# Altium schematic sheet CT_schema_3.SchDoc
size 608 x 329 mm
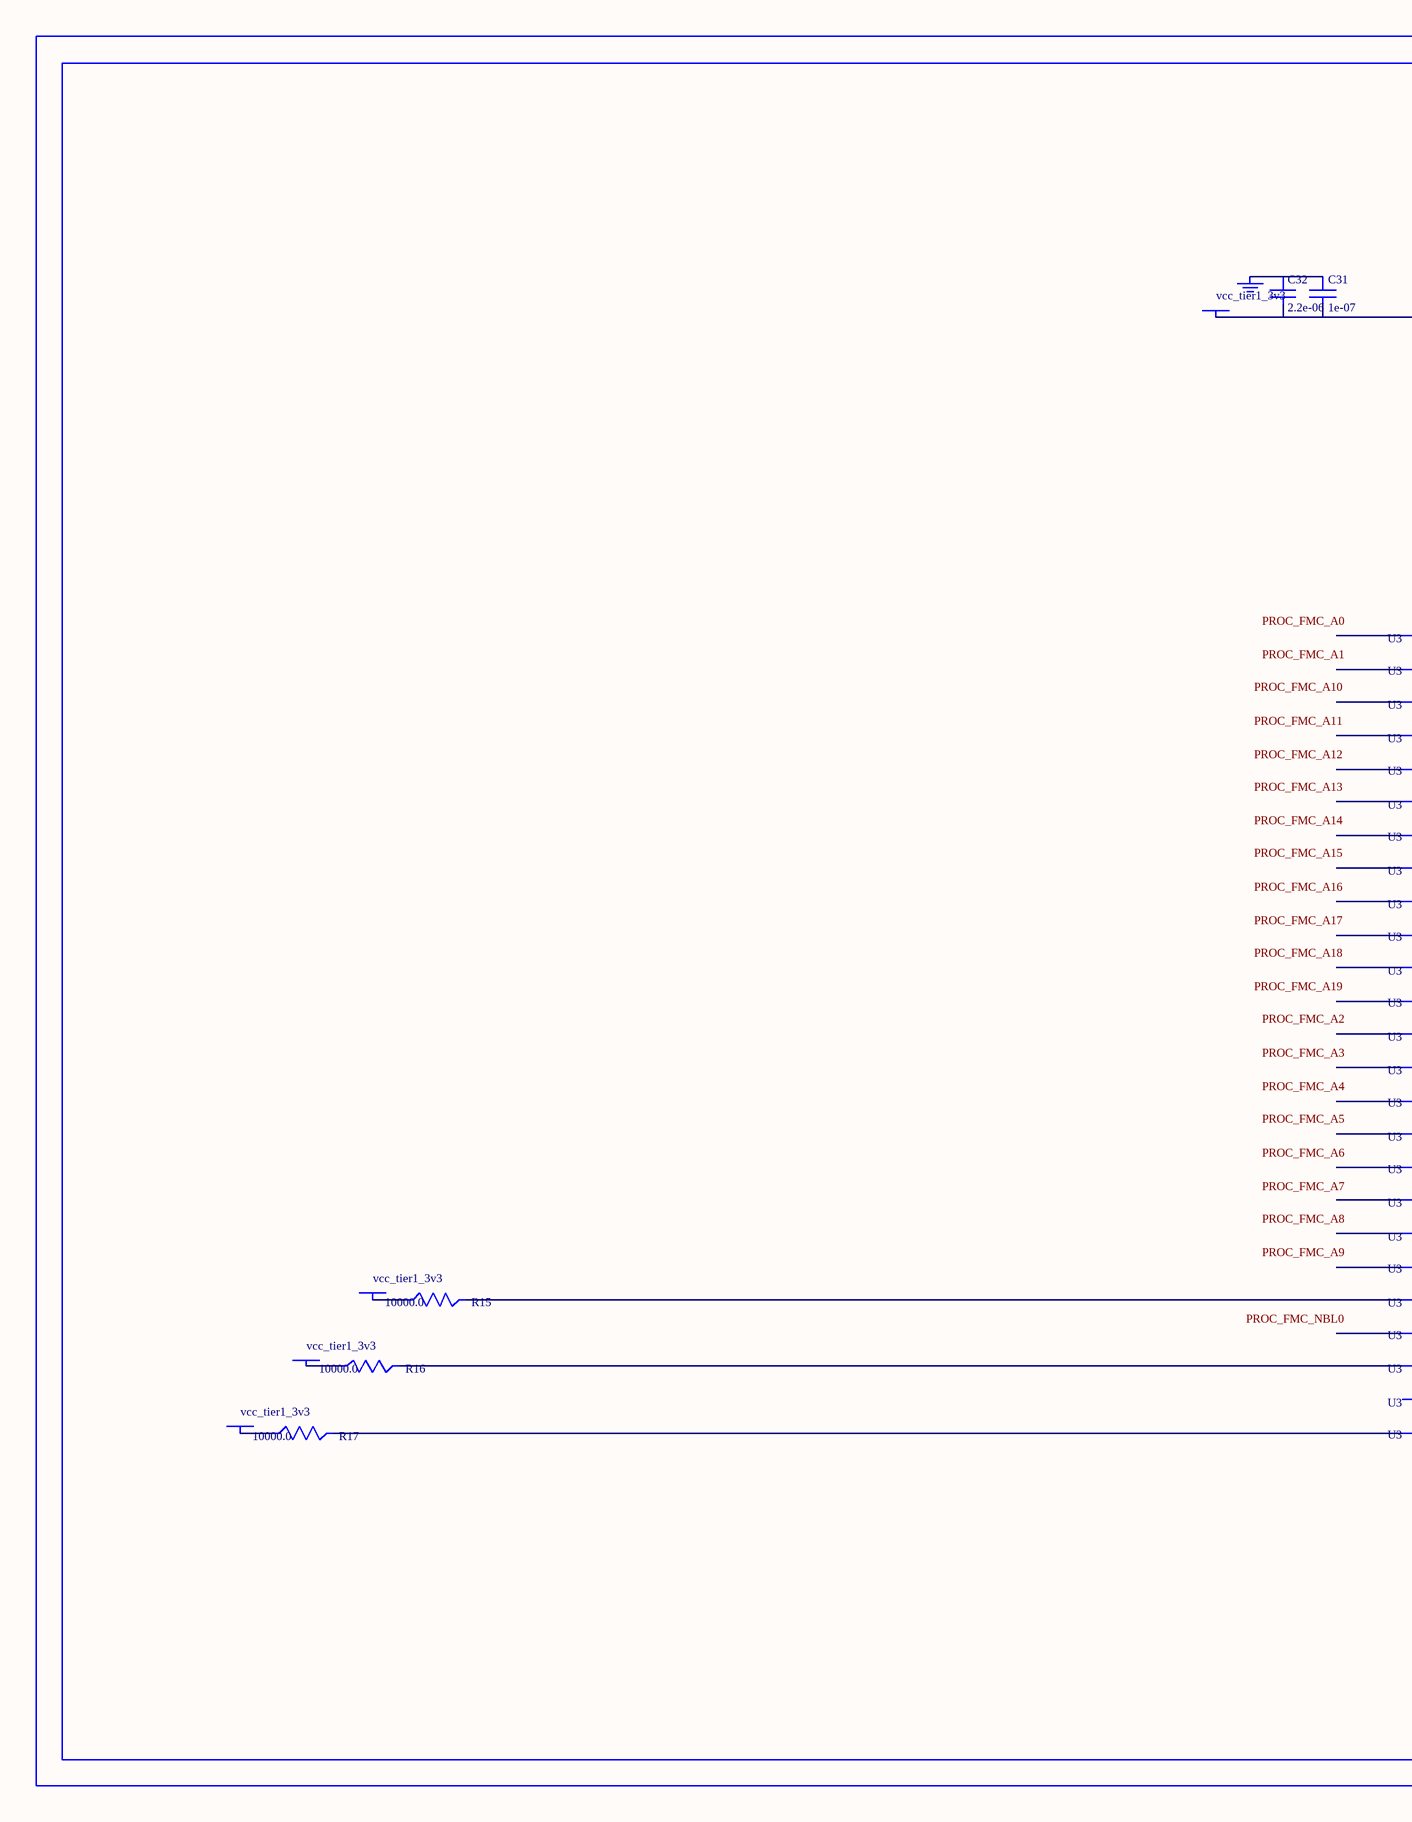
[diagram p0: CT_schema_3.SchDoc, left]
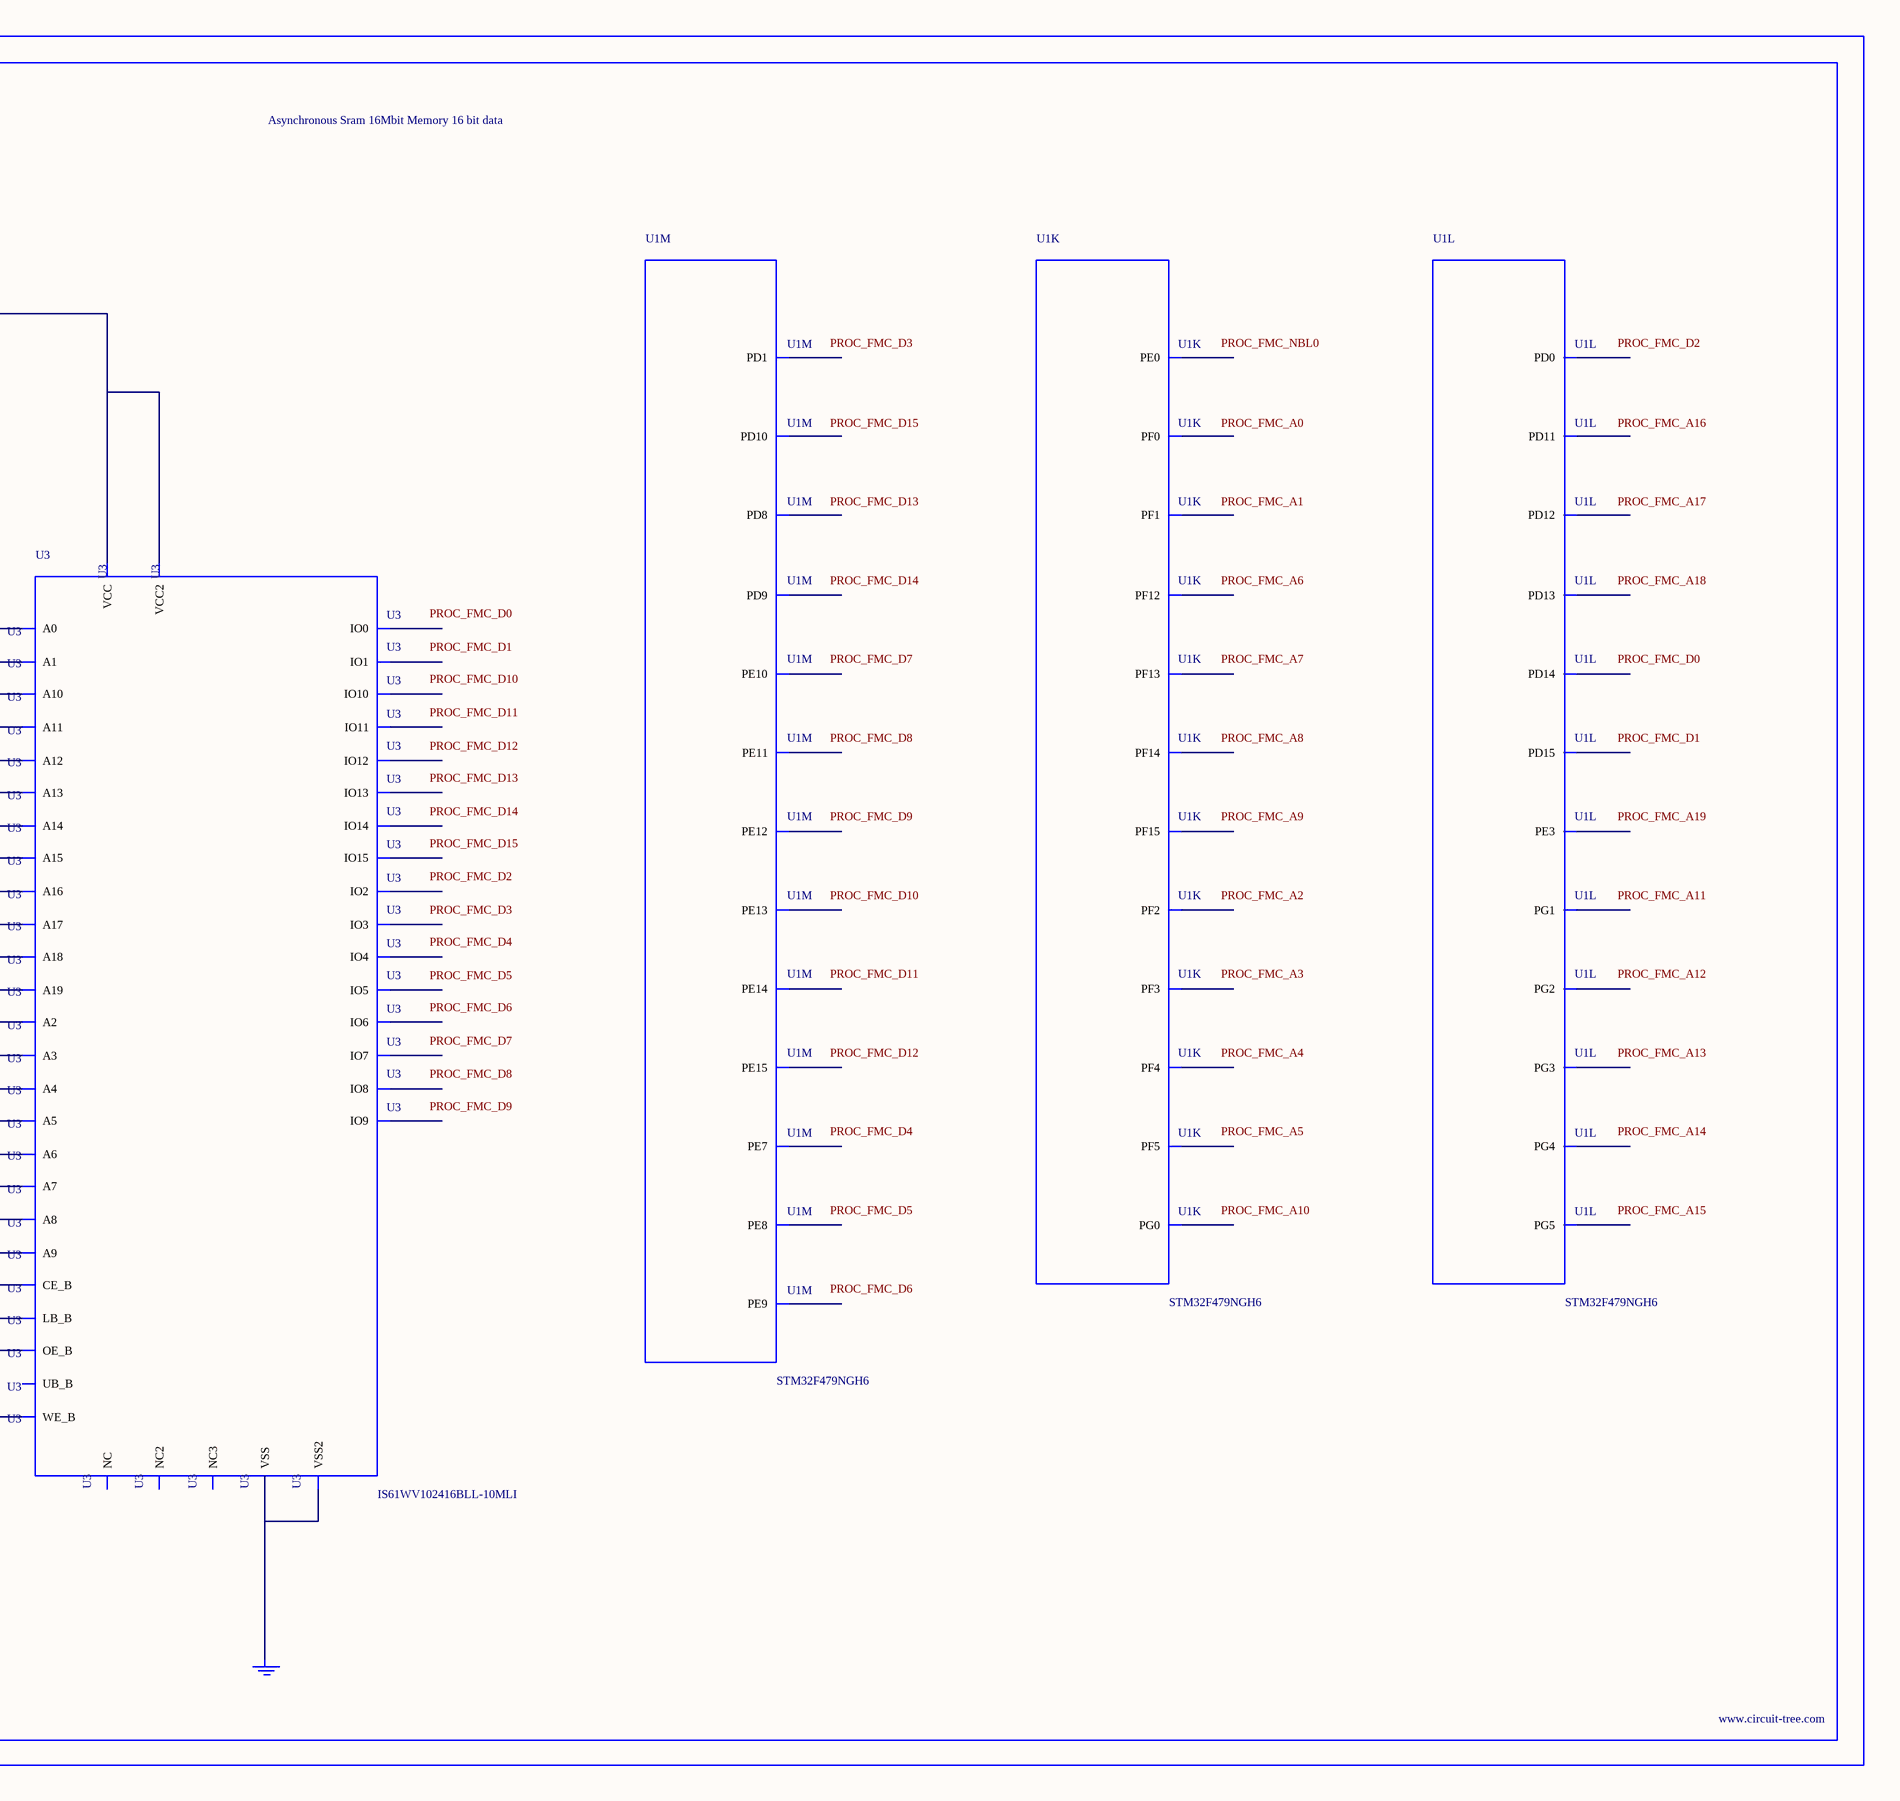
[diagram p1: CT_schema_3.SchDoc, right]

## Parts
BORDER2  (no value)
C31  1e-07  [C0402]
C32  2.2e-06  [C0603]
GND_INSTANCE_2_0  (no value)
GND_INSTANCE_2_1  (no value)
POWER_INSTANCE_2_0  vcc_tier1_3v3
POWER_INSTANCE_2_1  vcc_tier1_3v3
POWER_INSTANCE_2_2  vcc_tier1_3v3
POWER_INSTANCE_2_3  vcc_tier1_3v3
R15  10000.0  [R0603]
R16  10000.0  [R0603]
R17  10000.0  [R0603]
U1  STM32F479NGH6  [TFBGA216]  (parts K,L,M of 15)
U3  IS61WV102416BLL-10MLI  [IS61WV102416BLL-10MLI]

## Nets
NetC31_1: C31.1 C32.1 GND_INSTANCE_2_0.0(GND)
NetC31_2: C31.2 C32.2 POWER_INSTANCE_2_0.0(PWR) U3.D6(VCC) U3.E1(VCC2)
NetGND_INSTANCE_2_1_0: GND_INSTANCE_2_1.0(GND) U3.D1(VSS) U3.E6(VSS2)
NetPOWER_INSTANCE_2_1_0: POWER_INSTANCE_2_1.0(PWR) R15.1
NetPOWER_INSTANCE_2_2_0: POWER_INSTANCE_2_2.0(PWR) R16.1
NetPOWER_INSTANCE_2_3_0: POWER_INSTANCE_2_3.0(PWR) R17.1
NetR15_2: R15.2 U3.B5(CE_B)
NetR16_2: R16.2 U3.A2(OE_B)
NetR17_2: R17.2 U3.G5(WE_B)

Not connected (* = marked no-connect by the designer): U1 A2(PE3) A6(PE0) B12(PD0) C12(PD1) D2(PF0) E2(PF1) G2(PF2) H2(PF3) J2(PF4) K3(PF5) K13(PD15) K15(PD10) L12(PD14) L14(PD9) L15(PD8) M6(PF12) M7(PG1) M8(PF15) M10(PD12) M11(PD13) M12(PG3) M13(PG2) N6(PF13) N7(PG0) N9(PE8) N10(PD11) N11(PG5) N12(PG4) P6(PF14) P9(PE9) P10(PE11) P11(PE14) R8(PE7) R9(PE10) R10(PE12) R11(PE15) R12(PE13); U3 A1(LB_B) A3(A0) A4(A1) A5(A2) A6(NC) B1(IO8) B2(UB_B) B3(A3) B4(A4) B6(IO0) C1(IO9) C2(IO10) C3(A5) C4(A6) C5(IO1) C6(IO2) D2(IO11) D3(A17) D4(A7) D5(IO3) E2(IO12) E3(NC2) E4(A16) E5(IO4) F1(IO14) F2(IO13) F3(A14) F4(A15) F5(IO5) F6(IO6) G1(IO15) G2(A19) G3(A12) G4(A13) G6(IO7) H1(A18) H2(A8) H3(A9) H4(A10) H5(A11) H6(NC3)

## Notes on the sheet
- Labels drawn without touching a wire or pin: PROC_FMC_A0, PROC_FMC_A1, PROC_FMC_A2, PROC_FMC_A3, PROC_FMC_A4, PROC_FMC_A5, PROC_FMC_A6, PROC_FMC_A7, PROC_FMC_A8, PROC_FMC_A9, PROC_FMC_A10, PROC_FMC_A11, PROC_FMC_A12, PROC_FMC_A13, PROC_FMC_A14, PROC_FMC_A15, PROC_FMC_A16, PROC_FMC_A17, PROC_FMC_A18, PROC_FMC_A19, PROC_FMC_D0, PROC_FMC_D1, PROC_FMC_D2, PROC_FMC_D3, PROC_FMC_D4, PROC_FMC_D5, PROC_FMC_D6, PROC_FMC_D7, PROC_FMC_D8, PROC_FMC_D9, PROC_FMC_D10, PROC_FMC_D11, PROC_FMC_D12, PROC_FMC_D13, PROC_FMC_D14, PROC_FMC_D15, PROC_FMC_NBL0

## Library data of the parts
BORDER2 = BORDER_PAGE2
C31 = C0402C104K3RACTU
C32 = C0603C225K8RACTU
GND_INSTANCE_2_0 GND_INSTANCE_2_1 = GND
POWER_INSTANCE_2_0-POWER_INSTANCE_2_3 = PWR
R15-R17 = RC0603JR-0710KL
